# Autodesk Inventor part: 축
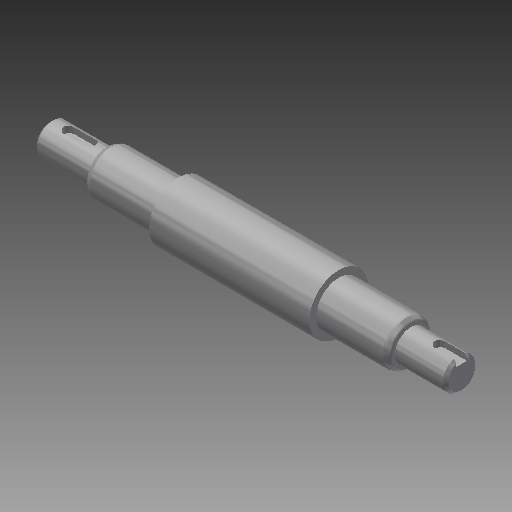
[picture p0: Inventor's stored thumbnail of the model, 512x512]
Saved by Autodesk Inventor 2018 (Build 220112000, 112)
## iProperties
Created: 2019-06
Part Number: 축
Material: 강철, 연강
Document SubType Name: Modeling
Designer: mduedu
Density: 1 g/cm^3
Appearance: 강철
Author: mduedu
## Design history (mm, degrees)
sketch "스케치1"
  geometry: L1 (0, 0)-(21, 0); L2 (21, 0)-(21, 6); L3 (21, 6)-(0, 6); L4 (0, 6)-(0, 0); L5 (21, 0)-(48, 0); L6 (48, 0)-(48, 8.5); L7 (48, 8.5)-(21, 8.5); L8 (21, 8.5)-(21, 0); L9 (48, 0)-(108, 0); L10 (108, 0)-(108, 11); L11 (108, 11)-(48, 11); L12 (48, 11)-(48, 0); L13 (108, 0)-(135, 0); L14 (135, 0)-(135, 8.5); L15 (135, 8.5)-(108, 8.5); L16 (108, 8.5)-(108, 0); L17 (135, 0)-(154, 0); L18 (154, 0)-(154, 6); L19 (154, 6)-(135, 6); L20 (135, 6)-(135, 0)
  constraints: 40 end point, 10 parallel, 5 horizontal, 5 perpendicular
  dimensions: "d3" = 60 distance of L10.end L11.end; "d4" = 17 diameter of L15 L13; "d5" = 22 diameter of L11 L9; "d6" = 17 diameter of L7 L5; "d7" = 12 diameter of L3 L1; "d40" = 19 distance of L18.end L19.end; "d41" = 12 diameter of L19 L17; "d42" = 46 distance between parallel lines of L10 L18; "d43" = 133 distance between parallel lines of L8 L18; "d44" = 154 distance between parallel lines of L4 L18
revolve "회전1" sketch "스케치1" stored, may be unused: angle "d9" = 90 deg
node "작업 평면1"
sketch "스케치2" dims "d10" = 12
  geometry: L1 (3.5, -2)-(-4.5, -2); L2 (-4.5, -2)-(-4.5, 2); L3 (-4.5, 2)-(3.5, 2); L4 (3.5, 2)-(3.5, -2); L5 (-10.5, 8.5)-(-10.5, -8.5) reference; 3 further points
  constraints: 8 end point, 2 midpoint, 2 parallel, 2 vertical alignment, 1 horizontal, 1 horizontal alignment, 1 perpendicular, 4 other
  dimensions: "d12" = 4 dimension on L5; "d13" = 4 distance between parallel lines of L3 L1
extrude "돌출1" cut sketch "스케치2" distance "d14" = 2.5; taper "d15" = 0 deg
sketch "스케치4"
  geometry: L1 (-143.5, 2)-(-135.5, 2); L2 (-135.5, 2)-(-135.5, -2); L3 (-135.5, -2)-(-143.5, -2); L4 (-143.5, -2)-(-143.5, 2); L5 (-143.5, 6)-(-143.5, -6) reference; 2 further points
  constraints: 8 end point, 2 parallel, 1 collinear, 1 horizontal, 1 horizontal alignment, 1 midpoint, 1 perpendicular, 1 vertical alignment, 2 other
  dimensions: "d50" = 10 dimension on L4; "d52" = 4 distance between parallel lines of L1 L3
extrude "돌출2" cut sketch "스케치4" distance "d53" = 2.5; taper "d54" = 0 deg
hole "구멍1" diameter "d18" = 3.242; stored, may be unused: countersink angle "d22" = 90 deg, drill point angle "d24" = 118 deg; dims "d16" = 10, "d17" = 10, "d19" = 8, "d20" = 4, "d21" = 2, "d23" = 10
sketch "스케치3"
  geometry: L1 (0, 0)-(2, 0); L2 (2, 0)-(2, -1.621); L3 (0, -2.776)-(0, 0); L4 (10, -1.621)-(0, -1.621) reference; L5 (0, -2.776)-(2, -1.621)
  constraints: 8 end point, 1 horizontal, 1 parallel, 1 perpendicular, 1 point on line
  dimensions: "d25" = 2 distance between parallel lines of L2 L3; "d27" = 30 deg angle of L1 L5
revolve "회전2" sketch "스케치3" stored, may be unused: angle "d29" = 90 deg
chamfer "모따기1" distance "d30" = 1.82; stored, may be unused: second distance "d31" = 2, angle "d32" = 30 deg
fillet "모깎기1" dims "d36" = 2, "d37" = 1
chamfer "모따기3" distance "d45" = 1.82; stored, may be unused: second distance "d46" = 2, angle "d47" = 30 deg
fillet "모깎기2" dims "d48" = 2, "d49" = 1
chamfer "모따기4" distance "d55" = 1; stored, may be unused: second distance "d56" = 2, angle "d57" = 30 deg
node "솔리드1"
